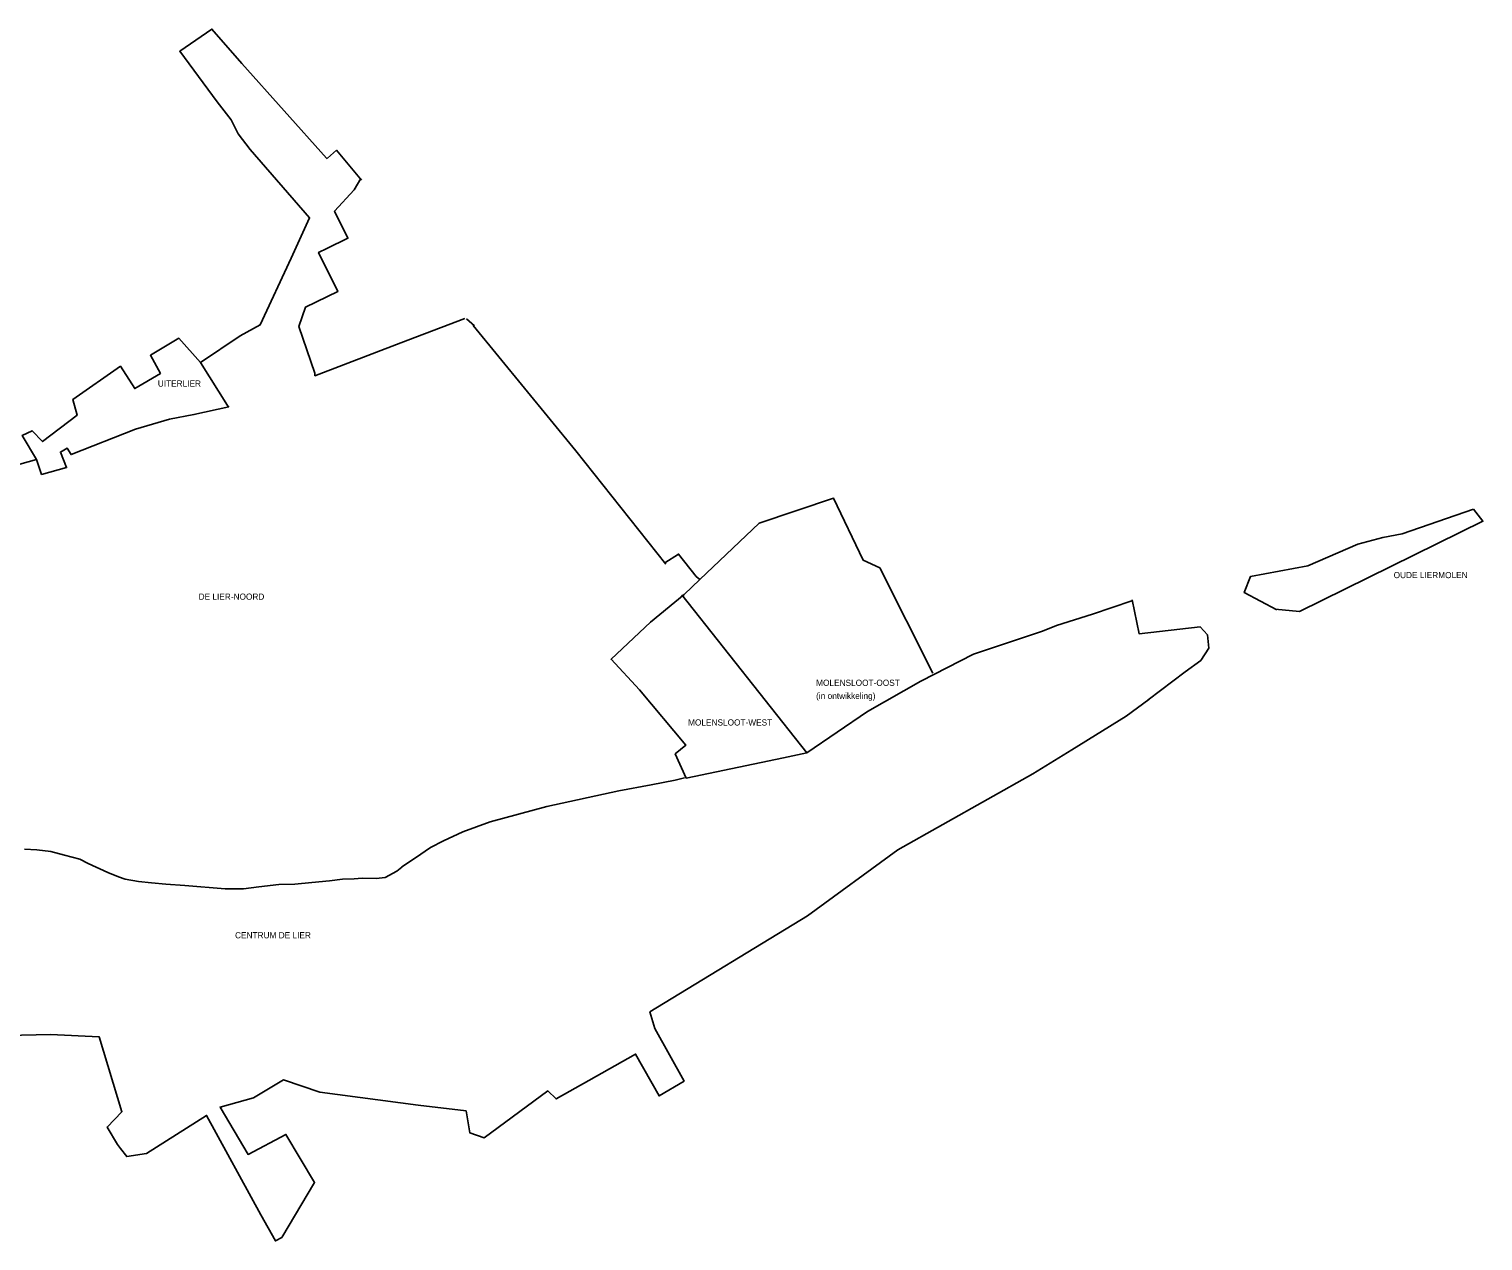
# Model space of a CAD drawing. Extents: x 69068 to 80855, y 440023 to 451362.
# Drawn here: x 76267 to 78382, y 443037 to 444800 of the extents above; entities that cross this region are included whole.
import ezdxf

# ---------------------------------------------------------------- set-up
doc = ezdxf.new("R2010")
doc.units = 0
doc.layers.add('Bemalingsgebiedsgrens', color=7, linetype='Continuous')
doc.layers.add('RIO_Leidingen', color=7, linetype='Continuous')

msp = doc.modelspace()

# ---------------------------------------------------------------- linework, layer by layer
at = {"layer": 'Bemalingsgebiedsgrens'}
msp.add_line((77216.7, 443977), (77398.6, 443747.3), dxfattribs=at)
for points in [[(76700.8, 444611.3), (76699.8, 444612.4), (76576.7, 444750.1), (76533.2, 444800.2), (76486.4, 444767.9), (76540.6, 444694.2), (76561.1, 444668.4), (76571.2, 444647.7), (76589, 444625.1), (76675.3, 444525.7), (76648.3, 444466.9), (76603.5, 444369.8), (76574.3, 444353.7), (76516.5, 444315.2), (76485, 444350.4), (76443.6, 444325.6), (76458.2, 444299.2), (76420.8, 444277.2), (76400, 444309.6), (76330.6, 444261.4), (76337.1, 444238.4), (76286.9, 444200.1), (76271.6, 444215.8), (76257.1, 444209), (76277.9, 444173.8), (76175.3, 444145.5)], [(76751, 444580.6), (76714.2, 444623.8), (76701.1, 444612.6)], [(76749.8, 444582.8), (76740.3, 444566.1), (76711.7, 444535.5), (76731, 444495.9), (76700.1, 444480.9), (76688.4, 444475.2), (76716.1, 444418.4), (76669.5, 444395.7), (76659.7, 444367.5), (76683, 444299.4), (76683, 444299.4), (76683, 444295.8), (76808, 444343.6), (76901.1, 444379.2)], [(76903.5, 444378.6), (76915, 444368.5)], [(77193.4, 444021.6), (77062.5, 444186.5), (76913, 444368.8)], [(76516.5, 444315.2), (76555.7, 444252.7), (76556.6, 444251.1), (76557.7, 444250.8), (76507, 444239.3), (76471.2, 444232.6), (76422.2, 444218.1), (76328.3, 444181.1), (76322.5, 444190.7), (76312.8, 444184.9), (76321.7, 444162.2), (76285.4, 444152.3), (76277.9, 444173.8)], [(77242.8, 443999.3), (77329.3, 444081.2), (77437.3, 444118), (77480.6, 444027.6), (77504.7, 444016.6), (77581.9, 443863.2)], [(78082.7, 443955.4), (78035, 443980.5), (78044.1, 444003.8), (78127.7, 444019.1), (78200.2, 444050.9), (78236.8, 444060.7), (78264.7, 444066), (78368.6, 444101.6)], [(78368.6, 444101.6), (78382.3, 444084.2), (78115.3, 443952.7), (78079.9, 443956.1)], [(77192.3, 444023.9), (77212.1, 444036.3), (77237.6, 444003.6)], [(77237.6, 444003.6), (77242.8, 443999.3), (77220, 443977.8), (77171.4, 443937.5)], [(77871.6, 443968.4), (77814.1, 443948.8), (77762, 443932.4), (77741.4, 443924.3)], [(77872.2, 443969.9), (77882.2, 443920.3), (77970.7, 443930.5), (77981.5, 443919.1), (77983.6, 443899.6), (77971.9, 443881.5), (77949.1, 443865.1), (77895.3, 443824.2)], [(77171.4, 443937.5), (77113.8, 443883.5), (77155.4, 443839.1), (77222.6, 443758.3), (77207.3, 443745.6), (77222.9, 443710.6), (77364.8, 443740.2), (77398.6, 443747.3), (77487.1, 443807.2), (77564.4, 443851.3), (77641, 443890.9), (77741.4, 443924.3)], [(76150.3, 443333.9), (76298.4, 443337.3), (76369.1, 443334.3), (76402.2, 443225), (76380.6, 443202.7), (76395.8, 443177.7), (76400.2, 443171.8), (76409.3, 443159.8), (76437.8, 443164.5), (76525.3, 443219.9), (76604.5, 443075), (76625.6, 443037.2), (76634.8, 443042.2), (76682.4, 443122.1), (76640.8, 443192.2), (76585.8, 443163), (76545, 443231.9), (76593.5, 443245.6), (76637.4, 443271.5), (76690.1, 443253.6), (76833.2, 443234.9), (76903, 443226.4), (76908.6, 443194.3), (76929.4, 443187.2), (77022.1, 443255.4), (77033.9, 443243.9), (77081.6, 443270.4), (77149.6, 443309), (77183.7, 443248.1), (77220.1, 443269.7), (77177.6, 443346), (77170.4, 443370.3), (77399.7, 443509.9), (77530.9, 443606.4), (77727.6, 443716.9), (77784.4, 443751.7), (77863.3, 443800.5), (77896.2, 443824.9)], [(76809.3, 443581.3), (76829.4, 443594.3), (76851.1, 443609.4), (76870.3, 443619.1), (76898.2, 443632.2), (76938, 443646.7), (77020.2, 443669), (77125.3, 443691.9), (77172.1, 443700.5), (77206.9, 443707.5), (77220.6, 443710.8)], [(76260.4, 443607.2), (76278.5, 443606.3), (76298.6, 443603.5), (76318.7, 443598.5), (76341, 443592.4), (76353.2, 443586.5), (76381.9, 443573.2), (76397.2, 443567), (76407, 443563.4), (76426.5, 443560.1), (76445.4, 443558.1), (76466.1, 443556.2), (76493.6, 443554.5), (76552.4, 443549.5), (76579.2, 443549.5), (76601.5, 443552.3), (76630.7, 443555.9), (76653.6, 443556.2), (76678.7, 443558.7), (76704, 443561.2), (76723, 443563.4), (76740.2, 443564), (76751.7, 443565.1), (76772.3, 443564.5), (76785.1, 443565.7), (76802.1, 443575.1), (76809.6, 443581)]]:
    msp.add_lwpolyline(points, dxfattribs=at)

# ---------------------------------------------------------------- texts
at = {"layer": 'RIO_Leidingen'}
for s, p in [('UITERLIER', (76454.4, 444280)), ('OUDE LIERMOLEN', (78252.4, 444001.4)), ('DE LIER-NOORD', (76513.8, 443970)), ('MOLENSLOOT-OOST', (77412.2, 443844.7)), ('(in ontwikkeling)', (77412.2, 443825.7)), ('MOLENSLOOT-WEST', (77225.9, 443787)), ('CENTRUM DE LIER', (76566.8, 443477.4))]:
    msp.add_text(s, height=9, dxfattribs=at).set_placement(p)

doc.saveas('drawing.dxf')
